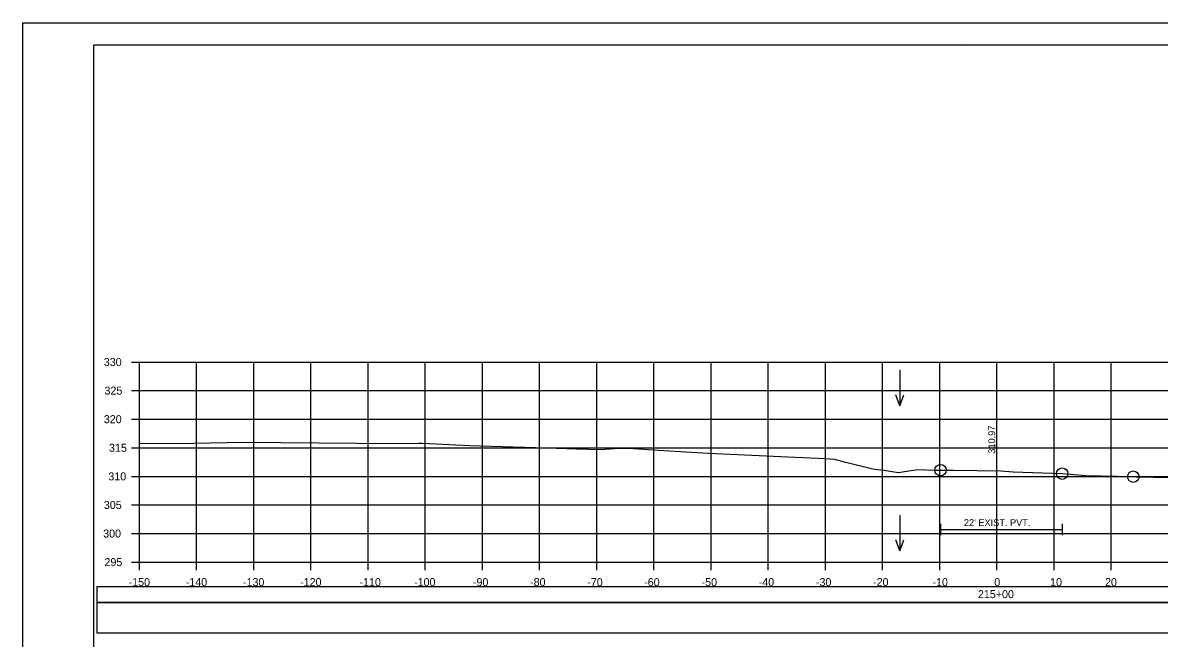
# Model space of a CAD drawing. Extents: x 1370538 to 1372872, y 376220 to 381127.
# Drawn here: x 1371538.2 to 1371737, y 379373.6 to 379481.3 of the extents above; entities that cross this region are included whole.
import ezdxf

# ---------------------------------------------------------------- set-up
doc = ezdxf.new("R2010")
doc.units = 0
for name, color, linetype in [('R_Border', 7, 'Continuous'), ('R_Border Notes', 7, 'Continuous'), ('R_Border PE', 7, 'Continuous'), ('R_Border Prem', 7, 'Continuous'), ('R_Dimension', 7, 'Continuous'), ('R_Grid', 7, 'Continuous'), ('R_No Plot', 7, 'Continuous'), ('R_Water', 7, 'Continuous'), ('R_Water Annot', 7, 'Continuous'), ('R_Xsect Elev', 7, 'Continuous'), ('T_Detection Zones', 7, 'Continuous')]:
    doc.layers.add(name, color=color, linetype=linetype)

msp = doc.modelspace()

# ---------------------------------------------------------------- linework, layer by layer
at = {"layer": 'R_Border'}
for p, q in [((1371698.78, 379393.66), (1371698.78, 379391.66)), ((1371720.05, 379393.66), (1371720.05, 379391.66)), ((1371698.78, 379392.66), (1371720.05, 379392.66))]:
    msp.add_line(p, q, dxfattribs=at)
at = {"layer": 'R_Border Notes'}
for p, q in [((1371550.63, 379477.41), (1371866.81, 379477.41)), ((1371550.63, 379271.95), (1371550.63, 379477.41)), ((1371703.15, 379477.15), (1371703.15, 379477.15)), ((1371703.15, 379477.15), (1371703.15, 379477.15))]:
    msp.add_line(p, q, dxfattribs=at)
at = {"layer": 'R_Border Prem'}
for p, q in [((1371557.23, 379421.95), (1371558.63, 379421.95)), ((1371558.63, 379386.95), (1371558.63, 379421.95)), ((1371557.23, 379416.95), (1371558.63, 379416.95)), ((1371557.23, 379411.95), (1371558.63, 379411.95)), ((1371557.23, 379406.95), (1371558.63, 379406.95)), ((1371557.23, 379401.95), (1371558.63, 379401.95)), ((1371557.23, 379396.95), (1371558.63, 379396.95)), ((1371557.23, 379391.95), (1371558.63, 379391.95)), ((1371557.23, 379386.95), (1371558.63, 379386.95)), ((1371558.63, 379386.95), (1371858.63, 379386.95)), ((1371558.63, 379385.55), (1371558.63, 379386.95)), ((1371568.63, 379385.55), (1371568.63, 379386.95)), ((1371578.63, 379385.55), (1371578.63, 379386.95)), ((1371588.63, 379385.55), (1371588.63, 379386.95)), ((1371598.63, 379385.55), (1371598.63, 379386.95)), ((1371608.63, 379385.55), (1371608.63, 379386.95)), ((1371618.63, 379385.55), (1371618.63, 379386.95)), ((1371628.63, 379385.55), (1371628.63, 379386.95)), ((1371638.63, 379385.55), (1371638.63, 379386.95)), ((1371648.63, 379385.55), (1371648.63, 379386.95)), ((1371658.63, 379385.55), (1371658.63, 379386.95)), ((1371668.63, 379385.55), (1371668.63, 379386.95)), ((1371678.63, 379385.55), (1371678.63, 379386.95)), ((1371688.63, 379385.55), (1371688.63, 379386.95)), ((1371698.63, 379385.55), (1371698.63, 379386.95)), ((1371708.63, 379385.55), (1371708.63, 379386.95)), ((1371718.63, 379385.55), (1371718.63, 379386.95)), ((1371728.63, 379385.55), (1371728.63, 379386.95))]:
    msp.add_line(p, q, dxfattribs=at)
at = {"layer": 'R_Dimension'}
msp.add_lwpolyline([(1371558.63, 379407.72), (1371568.1, 379407.77), (1371576.79, 379407.92), (1371603.18, 379407.67), (1371607.49, 379407.75), (1371608.08, 379407.74), (1371616.35, 379407.35), (1371629.84, 379406.92), (1371633.34, 379406.8), (1371635.11, 379406.74), (1371639.26, 379406.63), (1371642.57, 379406.87), (1371645.04, 379406.81), (1371649.35, 379406.54), (1371655.29, 379406.17), (1371658.17, 379405.98), (1371673.33, 379405.32), (1371678.73, 379405.06), (1371680.24, 379404.94), (1371681.93, 379404.48), (1371687.2, 379403.22), (1371688.87, 379403.01), (1371691.41, 379402.6), (1371692.44, 379402.8), (1371694.78, 379403.17), (1371697.87, 379403.06), (1371698.78, 379403.04), (1371701.03, 379403.01), (1371709.31, 379402.91), (1371711.49, 379402.77), (1371720.05, 379402.43), (1371724.19, 379402.08), (1371732.32, 379401.91), (1371732.36, 379401.91), (1371732.49, 379401.9), (1371732.99, 379401.89), (1371745.42, 379401.61)], dxfattribs=at)
at = {"layer": 'R_Grid'}
for p, q in [((1371558.63, 379421.95), (1371858.63, 379421.95)), ((1371558.63, 379386.95), (1371558.63, 379421.95)), ((1371558.63, 379421.95), (1371858.63, 379421.95)), ((1371558.63, 379386.95), (1371558.63, 379421.95)), ((1371568.63, 379386.95), (1371568.63, 379421.95)), ((1371568.63, 379386.95), (1371568.63, 379421.95)), ((1371578.63, 379386.95), (1371578.63, 379421.95)), ((1371578.63, 379386.95), (1371578.63, 379421.95)), ((1371588.63, 379386.95), (1371588.63, 379421.95)), ((1371588.63, 379386.95), (1371588.63, 379421.95)), ((1371598.63, 379386.95), (1371598.63, 379421.95)), ((1371598.63, 379386.95), (1371598.63, 379421.95)), ((1371608.63, 379386.95), (1371608.63, 379421.95)), ((1371608.63, 379386.95), (1371608.63, 379421.95)), ((1371618.63, 379386.95), (1371618.63, 379421.95)), ((1371618.63, 379386.95), (1371618.63, 379421.95)), ((1371628.63, 379386.95), (1371628.63, 379421.95)), ((1371628.63, 379386.95), (1371628.63, 379421.95)), ((1371638.63, 379386.95), (1371638.63, 379421.95)), ((1371638.63, 379386.95), (1371638.63, 379421.95)), ((1371648.63, 379386.95), (1371648.63, 379421.95)), ((1371648.63, 379386.95), (1371648.63, 379421.95)), ((1371658.63, 379386.95), (1371658.63, 379421.95)), ((1371658.63, 379386.95), (1371658.63, 379421.95)), ((1371668.63, 379386.95), (1371668.63, 379421.95)), ((1371668.63, 379386.95), (1371668.63, 379421.95)), ((1371678.63, 379386.95), (1371678.63, 379421.95)), ((1371678.63, 379386.95), (1371678.63, 379421.95)), ((1371688.63, 379386.95), (1371688.63, 379421.95)), ((1371688.63, 379386.95), (1371688.63, 379421.95)), ((1371698.63, 379386.95), (1371698.63, 379421.95)), ((1371698.63, 379386.95), (1371698.63, 379421.95)), ((1371708.63, 379386.95), (1371708.63, 379421.95)), ((1371708.63, 379386.95), (1371708.63, 379421.95)), ((1371718.63, 379386.95), (1371718.63, 379421.95)), ((1371718.63, 379386.95), (1371718.63, 379421.95)), ((1371728.63, 379386.95), (1371728.63, 379421.95)), ((1371728.63, 379386.95), (1371728.63, 379421.95)), ((1371558.63, 379416.95), (1371858.63, 379416.95)), ((1371558.63, 379416.95), (1371858.63, 379416.95)), ((1371558.63, 379411.95), (1371858.63, 379411.95)), ((1371558.63, 379411.95), (1371858.63, 379411.95)), ((1371558.63, 379406.95), (1371858.63, 379406.95)), ((1371558.63, 379406.95), (1371858.63, 379406.95)), ((1371558.63, 379401.95), (1371858.63, 379401.95)), ((1371558.63, 379401.95), (1371858.63, 379401.95)), ((1371558.63, 379396.95), (1371858.63, 379396.95)), ((1371558.63, 379396.95), (1371858.63, 379396.95)), ((1371558.63, 379391.95), (1371858.63, 379391.95)), ((1371558.63, 379391.95), (1371858.63, 379391.95)), ((1371558.63, 379386.95), (1371858.63, 379386.95)), ((1371558.63, 379386.95), (1371858.63, 379386.95))]:
    msp.add_line(p, q, dxfattribs=at)
at = {"layer": 'R_No Plot'}
msp.add_line((1371538.23, 379481.3), (1371871.56, 379481.3), dxfattribs=at)
for points in [[(1371538.22, 379481.3), (1371871.56, 379481.3), (1371871.56, 379267.96), (1371538.22, 379267.96)], [(1371784.55, 379477.41), (1371784.55, 379467.53), (1371820.28, 379467.53), (1371820.28, 379464.61), (1371843.48, 379464.61), (1371843.48, 379440.27), (1371866.81, 379440.27), (1371866.81, 379271.95), (1371550.63, 379271.95), (1371550.63, 379477.41)]]:
    msp.add_lwpolyline(points, close=True, dxfattribs=at)
for centre in [(1371698.78, 379403.04), (1371720.05, 379402.43), (1371732.49, 379401.9)]:
    msp.add_circle(centre, 1, dxfattribs=at)
at = {"layer": 'R_Water'}
msp.add_lwpolyline([(1371551.2, 379374.59), (1371866.33, 379374.59), (1371866.33, 379379.91), (1371551.2, 379379.91)], close=True, dxfattribs=at)
at = {"layer": 'R_Water Annot'}
for p, q in [((1371691.63, 379420.56), (1371691.63, 379414.27)), ((1371691.63, 379414.27), (1371690.93, 379416.19)), ((1371691.63, 379414.27), (1371692.33, 379416.19)), ((1371691.63, 379395.18), (1371691.63, 379388.9)), ((1371691.63, 379388.9), (1371690.93, 379390.82)), ((1371691.63, 379388.9), (1371692.33, 379390.82))]:
    msp.add_line(p, q, dxfattribs=at)
at = {"layer": 'R_Xsect Elev'}
msp.add_line((1371708.63, 379402.92), (1371708.63, 379412.92), dxfattribs=at)
at = {"layer": 'T_Detection Zones'}
msp.add_lwpolyline([(1371551.2, 379379.91), (1371866.33, 379379.91), (1371866.33, 379382.62), (1371551.2, 379382.62)], close=True, dxfattribs=at)

# ---------------------------------------------------------------- texts
at = {"layer": 'R_Border PE'}
for s, p in [('330', (1371552.4, 379421.25)), ('325', (1371552.52, 379416.25)), ('320', (1371552.4, 379411.25)), ('315', (1371553.31, 379406.25)), ('310', (1371553.19, 379401.25)), ('305', (1371552.41, 379396.25)), ('300', (1371552.29, 379391.25)), ('295', (1371552.52, 379386.25)), ('-150', (1371556.74, 379382.75)), ('-140', (1371566.74, 379382.75)), ('-130', (1371576.74, 379382.75)), ('-120', (1371586.74, 379382.75)), ('-110', (1371597.13, 379382.75)), ('-100', (1371606.68, 379382.75)), ('-90', (1371616.97, 379382.75)), ('-80', (1371626.97, 379382.75)), ('-70', (1371636.97, 379382.75)), ('-60', (1371646.93, 379382.75)), ('-50', (1371656.97, 379382.75)), ('-40', (1371666.97, 379382.75)), ('-30', (1371676.97, 379382.75)), ('-20', (1371686.97, 379382.75)), ('-10', (1371697.36, 379382.75)), ('0', (1371708.17, 379382.75)), ('10', (1371717.94, 379382.75)), ('20', (1371727.54, 379382.75)), ('215+00', (1371705.31, 379380.65))]:
    msp.add_text(s, height=1.4, dxfattribs=at).set_placement(p)
at = {"layer": 'R_Water'}
msp.add_text("22' EXIST. PVT.", height=1.2, dxfattribs=at).set_placement((1371702.86, 379393.26))
at = {"layer": 'R_Xsect Elev'}
msp.add_text('310.97', height=1.2, rotation=90, dxfattribs=at).set_placement((1371708.33, 379405.92))

doc.saveas('drawing.dxf')
